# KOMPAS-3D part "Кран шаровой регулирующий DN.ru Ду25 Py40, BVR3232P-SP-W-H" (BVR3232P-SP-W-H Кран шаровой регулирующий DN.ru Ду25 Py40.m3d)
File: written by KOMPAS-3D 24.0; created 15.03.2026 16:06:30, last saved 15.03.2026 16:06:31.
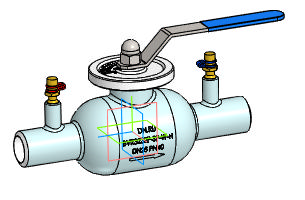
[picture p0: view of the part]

Document properties: Автор: Максим; Полное имя файла: D:\Rabota ebanaya\BVR3232P-SP-W-H Кран шаровой регулирующий Ду15-150\Типоразмеры\DN25\BVR3232P-SP-W-H Кран шаровой регулирующий DN.ru Ду25 Py40.m3d

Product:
- Body: Тело 1  | qty 1
    Масса: 4.076514
- Part/product: Кран шаровой регулирующий DN.ru Ду25 Py40  | designation BVR3232P-SP-W-H
    Масса: 2.3
    Раздел спецификации: Прочие изделия
    Примечание: D160-69408

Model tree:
1. Операция без истории:1

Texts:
  BVR3232P-SP-W-H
